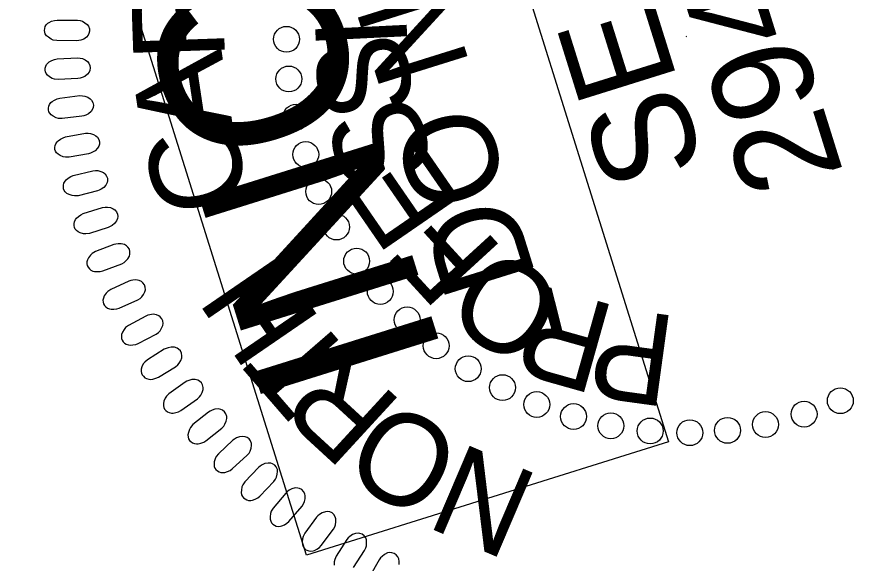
# Model space of a CAD drawing. Extents: x 473667 to 478950, y 494687 to 505998.
# Drawn here: x 473794.7 to 473846.5, y 505515.8 to 505549.7 of the extents above; entities that cross this region are included whole.
import ezdxf

# ---------------------------------------------------------------- set-up
doc = ezdxf.new("R2010")
doc.units = 0
doc.layers.add('Sheet PE Seal Cell', color=7, linetype='Continuous')
doc.layers.add('Sheet Sticker Incomplete CELL', color=7, linetype='Continuous')

msp = doc.modelspace()

# ---------------------------------------------------------------- linework, layer by layer
at = {"layer": 'Sheet PE Seal Cell'}
msp.add_line((473836.189, 505548.46), (473836.233, 505548.474), dxfattribs=at)
for points in [[(473798.442, 505548.188), (473797.215, 505548.201), (473796.996, 505548.241), (473796.858, 505548.295), (473796.689, 505548.409), (473796.581, 505548.507), (473796.502, 505548.62), (473796.463, 505548.725), (473796.444, 505548.838), (473796.466, 505548.95), (473796.497, 505549.069), (473796.558, 505549.173), (473796.659, 505549.276), (473796.739, 505549.335), (473796.89, 505549.401), (473797.07, 505549.459), (473797.23, 505549.48), (473798.486, 505549.473), (473798.656, 505549.449), (473798.795, 505549.403), (473798.954, 505549.312), (473799.092, 505549.197), (473799.17, 505549.1), (473799.229, 505548.942), (473799.246, 505548.792), (473799.205, 505548.643), (473799.154, 505548.539), (473799.053, 505548.413), (473798.883, 505548.295), (473798.702, 505548.23), (473798.572, 505548.202)], [(473798.521, 505545.855), (473797.296, 505545.791), (473797.076, 505545.817), (473796.933, 505545.862), (473796.758, 505545.965), (473796.643, 505546.056), (473796.558, 505546.164), (473796.513, 505546.267), (473796.486, 505546.378), (473796.501, 505546.491), (473796.525, 505546.612), (473796.579, 505546.719), (473796.673, 505546.829), (473796.749, 505546.893), (473796.896, 505546.968), (473797.072, 505547.037), (473797.23, 505547.068), (473798.485, 505547.14), (473798.655, 505547.126), (473798.797, 505547.089), (473798.96, 505547.008), (473799.106, 505546.903), (473799.191, 505546.81), (473799.259, 505546.657), (473799.286, 505546.508), (473799.254, 505546.357), (473799.21, 505546.25), (473799.117, 505546.118), (473798.954, 505545.989), (473798.778, 505545.913), (473798.65, 505545.877)], [(473798.758, 505543.513), (473797.54, 505543.373), (473797.318, 505543.385), (473797.173, 505543.421), (473796.992, 505543.513), (473796.872, 505543.597), (473796.78, 505543.699), (473796.728, 505543.798), (473796.695, 505543.908), (473796.702, 505544.021), (473796.718, 505544.144), (473796.766, 505544.254), (473796.853, 505544.37), (473796.925, 505544.438), (473797.066, 505544.522), (473797.237, 505544.603), (473797.394, 505544.643), (473798.641, 505544.794), (473798.812, 505544.791), (473798.956, 505544.763), (473799.125, 505544.692), (473799.276, 505544.596), (473799.367, 505544.509), (473799.444, 505544.36), (473799.481, 505544.214), (473799.458, 505544.061), (473799.421, 505543.951), (473799.336, 505543.814), (473799.181, 505543.675), (473799.011, 505543.588), (473798.885, 505543.543)], [(473799.184, 505541.195), (473797.977, 505540.979), (473797.754, 505540.977), (473797.608, 505541.004), (473797.421, 505541.084), (473797.296, 505541.16), (473797.198, 505541.257), (473797.14, 505541.352), (473797.1, 505541.459), (473797.101, 505541.573), (473797.109, 505541.696), (473797.149, 505541.81), (473797.229, 505541.93), (473797.296, 505542.003), (473797.432, 505542.097), (473797.598, 505542.186), (473797.751, 505542.237), (473798.987, 505542.466), (473799.158, 505542.474), (473799.303, 505542.455), (473799.476, 505542.395), (473799.633, 505542.309), (473799.728, 505542.228), (473799.815, 505542.083), (473799.862, 505541.94), (473799.848, 505541.785), (473799.818, 505541.674), (473799.742, 505541.531), (473799.597, 505541.383), (473799.432, 505541.285), (473799.309, 505541.233)], [(473799.724, 505538.889), (473798.532, 505538.596), (473798.31, 505538.58), (473798.162, 505538.598), (473797.97, 505538.667), (473797.841, 505538.735), (473797.737, 505538.825), (473797.673, 505538.917), (473797.627, 505539.021), (473797.62, 505539.135), (473797.62, 505539.258), (473797.654, 505539.374), (473797.725, 505539.499), (473797.789, 505539.576), (473797.918, 505539.678), (473798.078, 505539.778), (473798.227, 505539.838), (473799.447, 505540.144), (473799.616, 505540.163), (473799.763, 505540.153), (473799.939, 505540.103), (473800.101, 505540.028), (473800.202, 505539.953), (473800.298, 505539.814), (473800.353, 505539.674), (473800.35, 505539.519), (473800.325, 505539.406), (473800.259, 505539.258), (473800.123, 505539.102), (473799.965, 505538.994), (473799.845, 505538.934)], [(473800.404, 505536.629), (473799.233, 505536.263), (473799.012, 505536.233), (473798.863, 505536.242), (473798.668, 505536.298), (473798.534, 505536.358), (473798.425, 505536.441), (473798.355, 505536.529), (473798.303, 505536.63), (473798.288, 505536.743), (473798.281, 505536.866), (473798.307, 505536.984), (473798.371, 505537.113), (473798.43, 505537.195), (473798.552, 505537.303), (473798.705, 505537.414), (473798.851, 505537.483), (473800.048, 505537.865), (473800.216, 505537.895), (473800.363, 505537.894), (473800.542, 505537.856), (473800.709, 505537.79), (473800.814, 505537.721), (473800.918, 505537.589), (473800.982, 505537.453), (473800.988, 505537.298), (473800.972, 505537.184), (473800.915, 505537.032), (473800.789, 505536.867), (473800.638, 505536.75), (473800.523, 505536.683)], [(473800.745, 505535.568), (473799.6, 505535.129), (473799.409, 505535.015), (473799.297, 505534.917), (473799.179, 505534.751), (473799.111, 505534.621), (473799.077, 505534.488), (473799.077, 505534.376), (473799.099, 505534.264), (473799.158, 505534.167), (473799.228, 505534.066), (473799.321, 505533.989), (473799.452, 505533.927), (473799.548, 505533.9), (473799.712, 505533.89), (473799.901, 505533.899), (473800.057, 505533.935), (473801.234, 505534.378), (473801.384, 505534.46), (473801.498, 505534.552), (473801.615, 505534.692), (473801.705, 505534.847), (473801.745, 505534.966), (473801.745, 505535.135), (473801.71, 505535.281), (473801.619, 505535.407), (473801.535, 505535.486), (473801.396, 505535.569), (473801.195, 505535.62), (473801.003, 505535.618), (473800.872, 505535.601)], [(473801.668, 505533.302), (473800.552, 505532.791), (473800.368, 505532.666), (473800.263, 505532.561), (473800.155, 505532.388), (473800.096, 505532.254), (473800.07, 505532.119), (473800.078, 505532.007), (473800.106, 505531.897), (473800.171, 505531.803), (473800.248, 505531.707), (473800.345, 505531.637), (473800.48, 505531.583), (473800.577, 505531.562), (473800.741, 505531.563), (473800.929, 505531.583), (473801.084, 505531.629), (473802.229, 505532.145), (473802.375, 505532.236), (473802.483, 505532.335), (473802.591, 505532.482), (473802.671, 505532.642), (473802.703, 505532.764), (473802.693, 505532.932), (473802.649, 505533.076), (473802.55, 505533.195), (473802.461, 505533.27), (473802.317, 505533.344), (473802.114, 505533.382), (473801.923, 505533.369), (473801.792, 505533.342)], [(473802.731, 505531.139), (473801.65, 505530.561), (473801.474, 505530.424), (473801.375, 505530.312), (473801.279, 505530.133), (473801.228, 505529.996), (473801.21, 505529.859), (473801.225, 505529.748), (473801.26, 505529.639), (473801.331, 505529.55), (473801.414, 505529.459), (473801.516, 505529.395), (473801.654, 505529.349), (473801.752, 505529.335), (473801.916, 505529.346), (473802.102, 505529.378), (473802.253, 505529.433), (473803.364, 505530.02), (473803.503, 505530.12), (473803.605, 505530.225), (473803.703, 505530.38), (473803.774, 505530.545), (473803.798, 505530.668), (473803.777, 505530.835), (473803.723, 505530.976), (473803.618, 505531.089), (473803.524, 505531.158), (473803.377, 505531.223), (473803.171, 505531.248), (473802.981, 505531.222), (473802.853, 505531.187)], [(473803.871, 505529.081), (473802.828, 505528.435), (473802.661, 505528.288), (473802.57, 505528.169), (473802.485, 505527.985), (473802.443, 505527.845), (473802.434, 505527.707), (473802.455, 505527.597), (473802.497, 505527.491), (473802.573, 505527.406), (473802.662, 505527.321), (473802.767, 505527.263), (473802.907, 505527.227), (473803.007, 505527.218), (473803.17, 505527.239), (473803.353, 505527.283), (473803.501, 505527.348), (473804.573, 505528.003), (473804.705, 505528.111), (473804.8, 505528.223), (473804.889, 505528.384), (473804.949, 505528.553), (473804.965, 505528.677), (473804.934, 505528.843), (473804.872, 505528.98), (473804.759, 505529.086), (473804.662, 505529.149), (473804.51, 505529.204), (473804.303, 505529.216), (473804.114, 505529.179), (473803.989, 505529.136)], [(473805.161, 505527.039), (473804.16, 505526.329), (473804.003, 505526.172), (473803.92, 505526.048), (473803.846, 505525.859), (473803.813, 505525.716), (473803.813, 505525.579), (473803.841, 505525.47), (473803.889, 505525.367), (473803.97, 505525.286), (473804.064, 505525.207), (473804.173, 505525.156), (473804.315, 505525.128), (473804.415, 505525.126), (473804.576, 505525.158), (473804.757, 505525.213), (473804.901, 505525.287), (473805.929, 505526.008), (473806.054, 505526.125), (473806.142, 505526.242), (473806.221, 505526.408), (473806.269, 505526.58), (473806.278, 505526.705), (473806.236, 505526.868), (473806.166, 505527.001), (473806.047, 505527.1), (473805.945, 505527.157), (473805.791, 505527.203), (473805.583, 505527.202), (473805.398, 505527.153), (473805.275, 505527.102)], [(473806.598, 505525.183), (473805.644, 505524.412), (473805.497, 505524.244), (473805.421, 505524.116), (473805.36, 505523.922), (473805.335, 505523.778), (473805.344, 505523.641), (473805.379, 505523.534), (473805.434, 505523.435), (473805.52, 505523.36), (473805.619, 505523.285), (473805.731, 505523.242), (473805.874, 505523.223), (473805.974, 505523.227), (473806.133, 505523.269), (473806.31, 505523.335), (473806.448, 505523.418), (473807.429, 505524.203), (473807.547, 505524.326), (473807.627, 505524.449), (473807.695, 505524.62), (473807.733, 505524.794), (473807.734, 505524.92), (473807.682, 505525.08), (473807.603, 505525.209), (473807.478, 505525.299), (473807.374, 505525.349), (473807.216, 505525.386), (473807.009, 505525.373), (473806.827, 505525.311), (473806.708, 505525.253)], [(473808.121, 505523.441), (473807.217, 505522.612), (473807.082, 505522.436), (473807.014, 505522.302), (473806.964, 505522.106), (473806.95, 505521.96), (473806.967, 505521.823), (473807.008, 505521.719), (473807.069, 505521.623), (473807.16, 505521.554), (473807.263, 505521.486), (473807.377, 505521.449), (473807.522, 505521.44), (473807.621, 505521.45), (473807.777, 505521.501), (473807.95, 505521.579), (473808.082, 505521.67), (473809.012, 505522.515), (473809.122, 505522.646), (473809.195, 505522.774), (473809.251, 505522.948), (473809.278, 505523.125), (473809.271, 505523.25), (473809.209, 505523.406), (473809.123, 505523.53), (473808.992, 505523.613), (473808.885, 505523.656), (473808.725, 505523.683), (473808.52, 505523.656), (473808.342, 505523.584), (473808.226, 505523.518)], [(473809.711, 505521.757), (473808.862, 505520.872), (473808.736, 505520.687), (473808.677, 505520.551), (473808.641, 505520.351), (473808.635, 505520.204), (473808.661, 505520.069), (473808.709, 505519.968), (473808.776, 505519.876), (473808.87, 505519.813), (473808.977, 505519.751), (473809.094, 505519.722), (473809.239, 505519.722), (473809.337, 505519.738), (473809.49, 505519.799), (473809.657, 505519.887), (473809.784, 505519.987), (473810.659, 505520.888), (473810.76, 505521.026), (473810.824, 505521.158), (473810.87, 505521.334), (473810.886, 505521.514), (473810.871, 505521.638), (473810.8, 505521.79), (473810.706, 505521.908), (473810.57, 505521.983), (473810.46, 505522.019), (473810.299, 505522.035), (473810.096, 505521.996), (473809.923, 505521.913), (473809.812, 505521.84)], [(473811.404, 505520.173), (473810.612, 505519.237), (473810.498, 505519.045), (473810.448, 505518.905), (473810.424, 505518.703), (473810.428, 505518.556), (473810.462, 505518.423), (473810.516, 505518.325), (473810.589, 505518.237), (473810.687, 505518.179), (473810.798, 505518.126), (473810.916, 505518.104), (473811.06, 505518.112), (473811.158, 505518.134), (473811.306, 505518.205), (473811.467, 505518.304), (473811.588, 505518.411), (473812.405, 505519.366), (473812.497, 505519.51), (473812.553, 505519.646), (473812.588, 505519.825), (473812.592, 505520.004), (473812.57, 505520.128), (473812.488, 505520.275), (473812.387, 505520.386), (473812.247, 505520.453), (473812.135, 505520.482), (473811.974, 505520.489), (473811.773, 505520.436), (473811.605, 505520.342), (473811.499, 505520.263)], [(473813.295, 505518.669), (473812.563, 505517.684), (473812.462, 505517.486), (473812.42, 505517.343), (473812.409, 505517.14), (473812.422, 505516.994), (473812.465, 505516.863), (473812.525, 505516.768), (473812.603, 505516.686), (473812.705, 505516.635), (473812.818, 505516.587), (473812.938, 505516.573), (473813.082, 505516.59), (473813.177, 505516.619), (473813.321, 505516.699), (473813.476, 505516.807), (473813.589, 505516.922), (473814.344, 505517.926), (473814.427, 505518.076), (473814.475, 505518.214), (473814.498, 505518.396), (473814.491, 505518.574), (473814.461, 505518.697), (473814.371, 505518.838), (473814.262, 505518.943), (473814.119, 505519.001), (473814.005, 505519.023), (473813.844, 505519.019), (473813.646, 505518.954), (473813.485, 505518.85), (473813.384, 505518.764)]]:
    msp.add_lwpolyline(points, close=True, dxfattribs=at)
for points in [[(473815.586, 505515.565), (473816.277, 505516.614), (473816.35, 505516.769), (473816.389, 505516.91), (473816.401, 505517.092), (473816.383, 505517.271), (473816.345, 505517.391), (473816.246, 505517.527), (473816.131, 505517.625), (473815.984, 505517.672), (473815.869, 505517.688), (473815.709, 505517.673), (473815.516, 505517.596), (473815.362, 505517.482), (473815.266, 505517.39), (473815.182, 505517.29), (473814.514, 505516.261), (473814.426, 505516.057), (473814.393, 505515.911), (473814.395, 505515.708)], [(473818.413, 505515.74), (473818.413, 505515.923), (473818.384, 505516.101), (473818.339, 505516.218), (473818.232, 505516.347), (473818.111, 505516.438), (473817.961, 505516.476), (473817.845, 505516.484), (473817.686, 505516.46), (473817.499, 505516.372), (473817.352, 505516.247), (473817.262, 505516.15), (473817.186, 505516.044), (473816.583, 505514.975)]]:
    msp.add_lwpolyline(points, dxfattribs=at)
for centre in [(473811.439, 505548.285), (473811.582, 505545.826), (473812.029, 505543.463), (473812.629, 505541.148), (473813.43, 505538.854), (473814.535, 505536.655), (473815.781, 505534.542), (473817.245, 505532.664), (473818.908, 505530.906), (473820.705, 505529.299), (473822.694, 505527.877), (473824.814, 505526.705), (473845.735, 505525.893), (473826.936, 505525.659), (473829.215, 505524.912), (473843.49, 505525.065), (473831.523, 505524.341), (473841.1, 505524.417), (473833.961, 505524.019), (473836.416, 505523.911), (473838.749, 505524.057)]:
    msp.add_circle(centre, 0.801, dxfattribs=at)
at = {"layer": 'Sheet Sticker Incomplete CELL'}
msp.add_lwpolyline([(473835.104, 505523.354), (473812.679, 505516.329), (473768.733, 505656.606), (473791.158, 505663.632)], close=True, dxfattribs=at)

# ---------------------------------------------------------------- texts
at = {"layer": 'Sheet PE Seal Cell'}
for s, height, rotation, p in [('29470', 6.2363, 107.3761, (473845.956, 505539.979)), ('SEAL', 6.2363, 107.3761, (473837.359, 505540.399)), ('R', 5.669, 92.0037, (473807.635, 505547.023)), ('I', 5.669, 92.8042, (473818.947, 505547.778)), ('S', 5.669, 100.744, (473819.481, 505543.962)), ('A', 5.669, 98.4931, (473808.135, 505542.772)), ('S', 5.669, 108.6838, (473820.732, 505540.308)), ('C', 5.669, 104.9824, (473809.304, 505538.343)), ('E', 5.669, 124.5634, (473822.475, 505537.954)), ('F', 5.669, 132.5032, (473824.956, 505535.179)), ('H', 5.669, 124.4505, (473813.644, 505530.79)), ('O', 5.669, 148.3828, (473829.057, 505532.59)), ('R', 5.669, 164.2624, (473831.999, 505531.715)), ('P', 5.669, 172.2022, (473835.711, 505531.111)), ('T', 5.669, 130.9399, (473815.939, 505528.178)), ('R', 5.669, 137.4292, (473818.733, 505525.678)), ('O', 5.669, 150.4079, (473822.662, 505523.267)), ('N', 5.669, 156.8973, (473827.246, 505521.196))]:
    msp.add_text(s, height=height, rotation=rotation, dxfattribs=at).set_placement(p)
at = {"layer": 'Sheet Sticker Incomplete CELL'}
for s, height, p in [('INCOMPLETE PLANS', 11.52, (473821.263, 505528.397)), ('DO NOT USE FOR R/W ACQUISITION', 5.76, (473826.924, 505533.576))]:
    msp.add_text(s, height=height, rotation=107.3948, dxfattribs=at).set_placement(p)

doc.saveas('drawing.dxf')
